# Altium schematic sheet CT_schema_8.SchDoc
size 287 x 160 mm
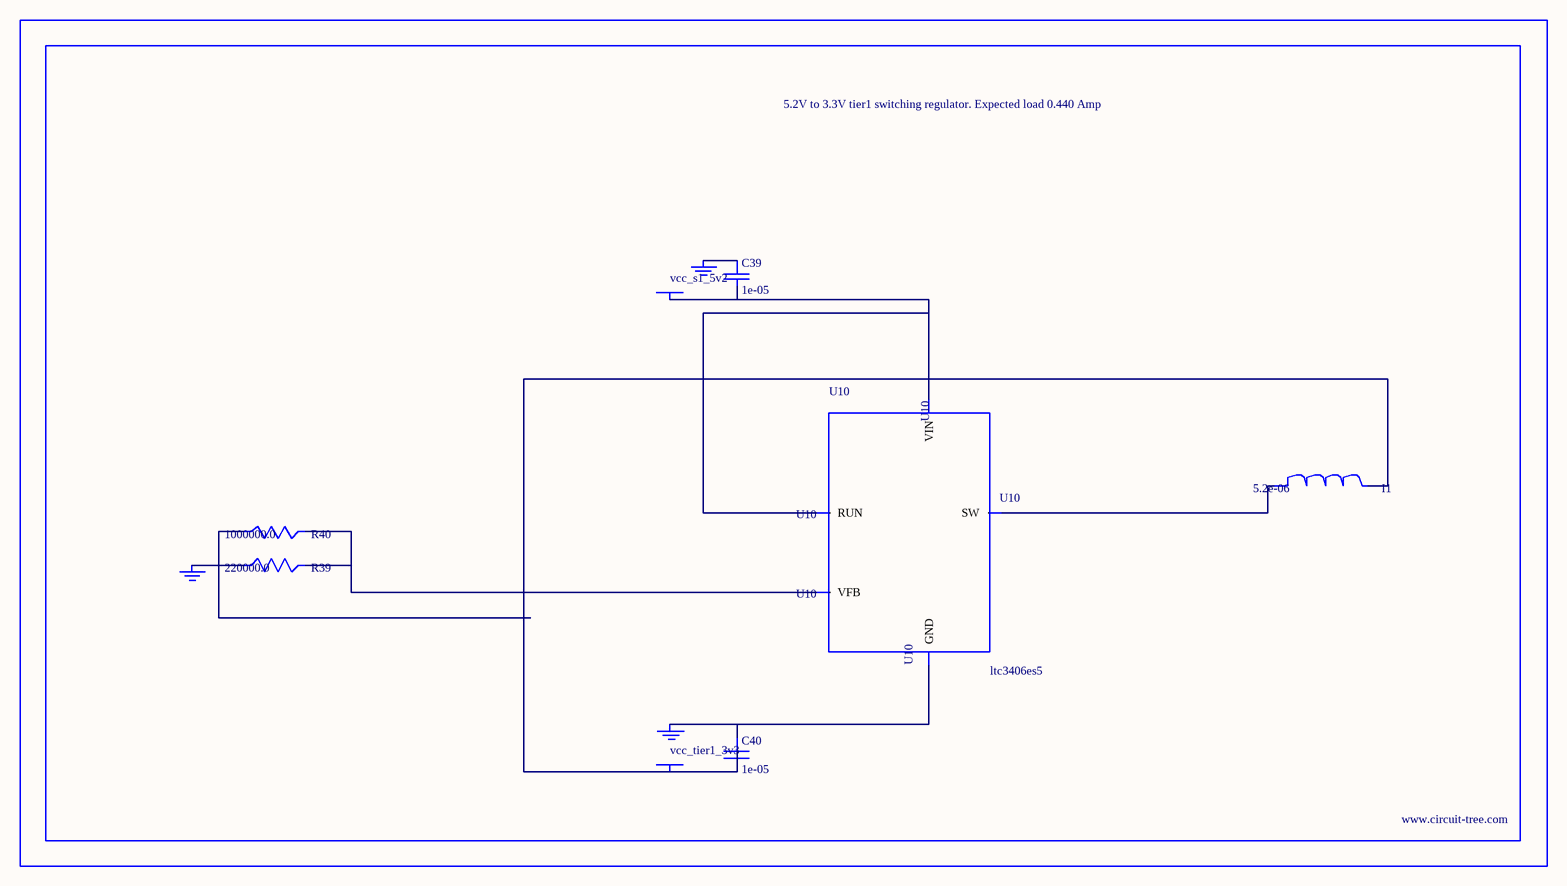
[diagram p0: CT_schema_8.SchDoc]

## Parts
BORDER7  (no value)
C39  1e-05  [C0805]
C40  1e-05  [C0805]
GND_INSTANCE_7_0  (no value)
GND_INSTANCE_7_1  (no value)
GND_INSTANCE_7_2  (no value)
I1  5.2e-06  [DR1040]
POWER_INSTANCE_7_0  vcc_tier1_3v3
POWER_INSTANCE_7_1  vcc_s1_5v2
R39  220000.0  [R0603]
R40  1000000.0  [R0603]
U10  ltc3406es5  [TSOT-23-5]

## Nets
NetC39_1: C39.1 GND_INSTANCE_7_1.0(GND)
NetC39_2: C39.2 POWER_INSTANCE_7_1.0(PWR) U10.1(RUN) U10.4(VIN)
NetC40_1: C40.1 GND_INSTANCE_7_0.0(GND) U10.2(GND)
NetC40_2: C40.2 I1.2 POWER_INSTANCE_7_0.0(PWR) R40.1
NetGND_INSTANCE_7_2_0: GND_INSTANCE_7_2.0(GND) R39.1
NetI1_1: I1.1 U10.3(SW)
NetR39_2: R39.2 R40.2 U10.5(VFB)

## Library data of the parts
BORDER7 = BORDER_PAGE7
C39 C40 = C0805C106K8RACTU
GND_INSTANCE_7_0-GND_INSTANCE_7_2 = GND
I1 = DR1040-5R2-R
POWER_INSTANCE_7_0 POWER_INSTANCE_7_1 = PWR
R39 = RC0603JR-07220KL
R40 = RC0603JR-071ML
